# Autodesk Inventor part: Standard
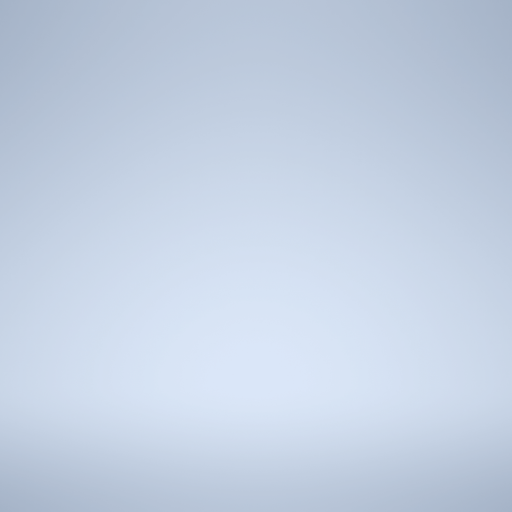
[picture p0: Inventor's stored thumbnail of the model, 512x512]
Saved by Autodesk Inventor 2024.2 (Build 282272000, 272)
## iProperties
Created: 2005-05
Part Number: Standard
Document SubType Name: Modeling
Designer: JWe
Density: 1 g/cm^3
Material: Generic
Appearance: Default
Author: JWe
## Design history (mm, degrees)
